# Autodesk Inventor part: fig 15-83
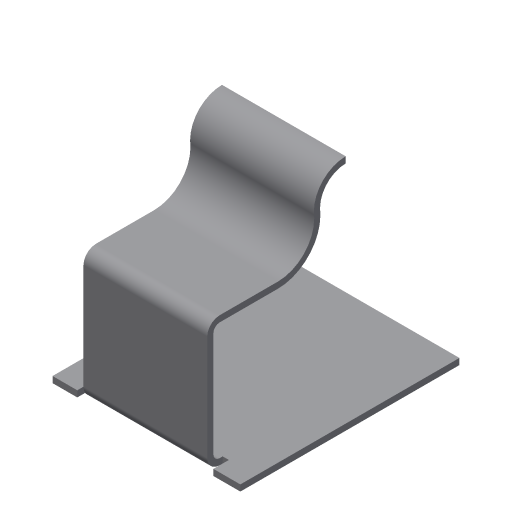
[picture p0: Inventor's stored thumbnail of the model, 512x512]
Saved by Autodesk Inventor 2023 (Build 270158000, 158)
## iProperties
Created: 2002-04
Part Number: fig 15-83
Document SubType Name: Sheet Metal
Density: 1 g/cm^3
Sheet Metal Rule: Default
Material: Generic
Appearance: Default
Control State: 0
Master: False
Checked Out: False
Shininess: 77.0
Angle Display Precision: 2
Document Length Units: 11269
Document Angle Units: 11279
Document Time Units: 11290
Document Mass Units: 11283
Document Length Units Precision: 3
Document Angle Units Precision: 2
Compacted: True
Density: 0.0
Volumn: 0.0
Area: 0.0
PropertySet Name: Model Information
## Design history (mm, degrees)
node "Face1"
  sketch "Sketch1"
    geometry: L1 (-24.824, 17.882)-(5.529, 17.882); L2 (5.529, 17.882)-(5.529, -17.529); L3 (5.529, -17.529)-(-24.824, -17.529); L4 (-24.824, -17.529)-(-24.824, 17.882)
    constraints: 8 end point, 2 parallel, 1 horizontal, 1 perpendicular
node "Flange1"
node "Contour Flange6"
  sketch "Sketch5"
    geometry: L1 (0, 1)-(0, 11.431); A1 r 5.855 centre (-5.855, 11.431) between (0, 11.431) and (-6.422, 17.259); A2 r 5.142 centre (-6.92, 22.376) between (-12.062, 22.382) and (-6.422, 17.259)
    constraints: 4 point on circle, 2 centre point, 2 end point, 2 tangent
body "Solid1"
face "Plate1" dims "d42" = 1 (= Thickness)
sketch "Sketch3"
  geometry: L1 (25.353, 0)-(5.353, 0); L2 (5.353, 0)-(5.353, 20); L3 (5.353, 20)-(25.353, 20); L4 (25.353, 20)-(25.353, 0)
  constraints: 8 end point
face "Plate3" dims "d5" = 20, "d6" = 90 deg, "d7" = 1 (= BendRadius), "d11" = 5, "d12" = 20, "d42" = 1 (= Thickness), "MinimumRemnant" = 2 (= 2 x Thickness), "BendReliefWidth" = 1 (= Thickness)
bend "Bend2" dims "d5" = 20, "d6" = 90 deg, "d7" = 1 (= BendRadius), "d21" = 1 (= BendReliefWidth), "d22" = 0.5 (= BendReliefDepth), "d23" = 2 (= MinimumRemnant), "d42" = 1 (= Thickness), "SeamGap" = 0.01, "MinimumRemnant" = 2 (= 2 x Thickness), "BendReliefWidth" = 1 (= Thickness), "TransitionRadius" = 1 (= BendRadius)
face "Plate8" dims "d33" = 1 (= BendReliefWidth), "d34" = 0.5 (= BendReliefDepth), "d35" = 2 (= MinimumRemnant), "d36" = 1 (= BendRadius), "d37" = 1 (= BendRadius), "d38" = 1, "d39" = 4 (= CornerReliefSize), "d40" = 1 (= GapSize), "d41" = 1 (= JacobiRadiusSize), "d42" = 1 (= Thickness), "SeamGap" = 0.01
bend "Bend7" dims "d33" = 1 (= BendReliefWidth), "d34" = 0.5 (= BendReliefDepth), "d35" = 2 (= MinimumRemnant), "d36" = 1 (= BendRadius), "d37" = 1 (= BendRadius), "d38" = 1, "d42" = 1 (= Thickness), "SeamGap" = 0.01
feature "Corner1" dims "d38" = 1, "d39" = 4 (= CornerReliefSize), "d40" = 1 (= GapSize), "d41" = 1 (= JacobiRadiusSize)
other parameters: "Thickness" = 1, "BendRadius" = 1 (= Thickness), "BendReliefDepth" = 0.5 (= 0.5 x Thickness), "CornerReliefSize" = 4 (= 4 x Thickness), "d0" = 1 (= BendRadius), "d4" = 1 (= BendRadius), "JacobiRadiusSize" = 1 (= Thickness), "GapSize" = 1 (= Thickness)
